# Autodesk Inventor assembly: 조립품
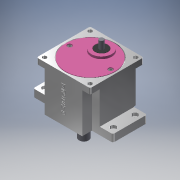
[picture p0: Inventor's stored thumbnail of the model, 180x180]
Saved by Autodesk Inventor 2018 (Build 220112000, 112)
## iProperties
Created: 2020-07
Part Number: 조립품
Material: 일반
Document SubType Name: Assembly
Designer: Admin
Author: Admin
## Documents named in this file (10)
- C:\Users\Admin\Desktop\700707V1007\조립품.iam
- C:\Users\Admin\Desktop\700707V1007\본체.ipt
- C:\Users\Admin\Desktop\700707V1007\커버.ipt
- C:\Users\Admin\Desktop\700707V1007\베어링 6003.ipt
- C:\Users\Admin\Desktop\700707V1007\베어링 608.ipt
- C:\Users\Admin\Desktop\700707V1007\서브 축.ipt
- C:\Users\Admin\Desktop\700707V1007\메인 축.ipt
- C:\Users\Admin\Desktop\700707V1007\볼트 M4.ipt
- C:\Users\Admin\Desktop\700707V1007\오일 실 17 32 8.ipt
- C:\Users\Admin\Desktop\700707V1007\오일 실 8 22 7.ipt
